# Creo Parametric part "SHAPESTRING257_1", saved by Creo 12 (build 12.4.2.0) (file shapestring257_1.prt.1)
Units: Custom; MM, KILOGRAM, SECS

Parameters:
  PTC_WM_ITERATION = "0"
  PTC_WM_VERSION = "-.0"
  PTC_WM_LIFECYCLE_STATE = "In Work"
  PTC_WM_LIFECYCLE = "MO_CADDocument"
  PTC_WM_CREATED_BY = "Maximilian Roepper (Z0017RMS: MO)"
  PTC_WM_CREATED_ON = "18-Sep-26 11:36:42 AM"
  PTC_WM_MODIFIED_BY = "Maximilian Roepper (Z0017RMS: MO)"
  PTC_WM_MODIFIED_ON = "18-Sep-26 11:36:46 AM"
  PDMLINKNUMBER = "PDM000071454786"
  PTC_WM_NAME = "shapestring257_1.prt"
  PTC_WM_NUMBER = "PDM000071454786"

Other parameters: WEIGHT, WEIGHT_FACTOR, WEIGHT_ADD, _MASS_TEMP, _DIFF_TEMP, MC_ERRORS, SUPPLIER

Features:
  1. coordinate system
  2. datum plane "PRT_YZ"
  3. datum plane "PRT_XY"
  4. datum plane "PRT_XZ"
  5. coordinate system
  6. datum axis
  7. datum axis
  8. datum axis
  9. coordinate system
  10. imported feature
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
Other named items: PRT, SIEMENS_MO, DRW_VIEW_ORG, PRT_X, PRT_Y, PRT_Z, CS0, ROUGH_GROB

Layers: 00_STD_CSYS-KSYS, 01_STD_PLANES-EBENEN, 02_STD_AXES-ACHSEN, 03_STD_CSYS-KSYS, 24_IMPORT_FEAT-IMPORT_KE, WHITE

Surfaces: 1 plane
